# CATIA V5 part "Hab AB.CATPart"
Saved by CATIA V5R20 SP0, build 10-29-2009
Part number: Hab AB
Bounding box of the stored display mesh (mm): x -20 to -10, y -419.33 to -159.426, z -16.587 to 9.996
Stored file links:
  D:\Dropbox\IAO_2012\IAO_2012_766_vlaroche\vlaroche\vlaroche\IAO\A rendre\Hab AB.CATPart
  D:\Catia\IAO\A rendre\Assemblage.CATProduct
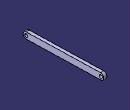
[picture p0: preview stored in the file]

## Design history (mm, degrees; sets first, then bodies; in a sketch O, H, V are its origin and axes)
Set1
  Point1: linked copy from another document
  Point2: linked copy from another document
Body1 (main body)
  Sketch1 on yz-plane, origin (0, 0, 0), H (0, 1, 0), V (0, 0, 1)
    construction line L1 (-409.3323, -6.5908) -> (-169.4228, 0)
    point P1 (-409.3323, -6.5908)
    point P2 (-169.4228, 0)
    line L2 (-409.607, 3.4054) -> (-169.6975, 9.9962)
    line L3 (-169.1482, -9.9962) -> (-409.0577, -16.5871)
    arc A1 centre (-169.4228, 0) radius 10 from (-169.6975, 9.9962) to (-169.1482, -9.9962) cw
    arc A2 centre (-409.3323, -6.5908) radius 10 from (-409.0577, -16.5871) to (-409.607, 3.4054) cw
    reference projected point E1 (-409.3323, -6.5908) from Point1
    reference projected point E2 (-169.4228, 0) from Point2
    circle A3 centre (-169.4228, 0) radius 5
    circle A4 centre (-409.3323, -6.5908) radius 5
    distance L1 L2 = 10
    radius A3 = 5
    radius A4 = 5
    tangency: A1 L2, A2 L2, A1 L3, A2 L3
    coincidence: P1 E1, P2 E2
  Pad1: profile Sketch1, direction (1, 0, 0), length -10, opposite side length 20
